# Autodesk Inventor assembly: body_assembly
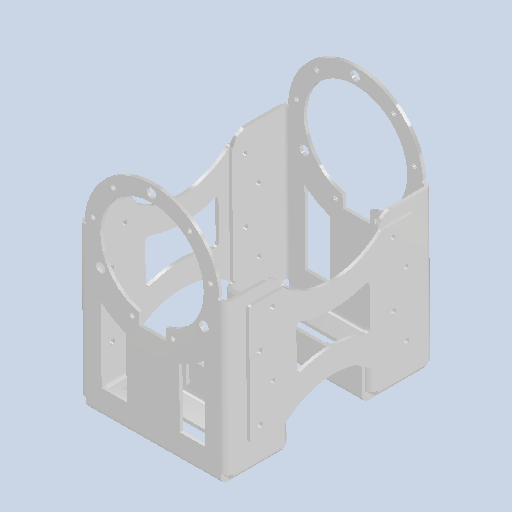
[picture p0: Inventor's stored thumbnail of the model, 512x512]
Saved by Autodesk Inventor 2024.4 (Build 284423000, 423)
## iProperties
Created: 2026-01
Part Number: body_assembly
Document SubType Name: Assembly
Designer: AdminForWorker
Title: body_assembly
Author: AdminForWorker
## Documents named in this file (3)
- c:\worker\convert-fusion-r06-cosv3\tmp\job-1\14\temp\files\7069be28-f26d-4d32-a85d-de0caccc6a05\body_assembly.iam
- c:\worker\convert-fusion-r06-cosv3\tmp\job-1\14\temp\files\7069be28-f26d-4d32-a85d-de0caccc6a05\front_body2.ipt
- c:\worker\convert-fusion-r06-cosv3\tmp\job-1\14\temp\files\7069be28-f26d-4d32-a85d-de0caccc6a05\front_body3.ipt
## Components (4 placed, 2 different names)
1. front_body2:1
2. front_body3:1
3. front_body2:2
4. front_body3:2
